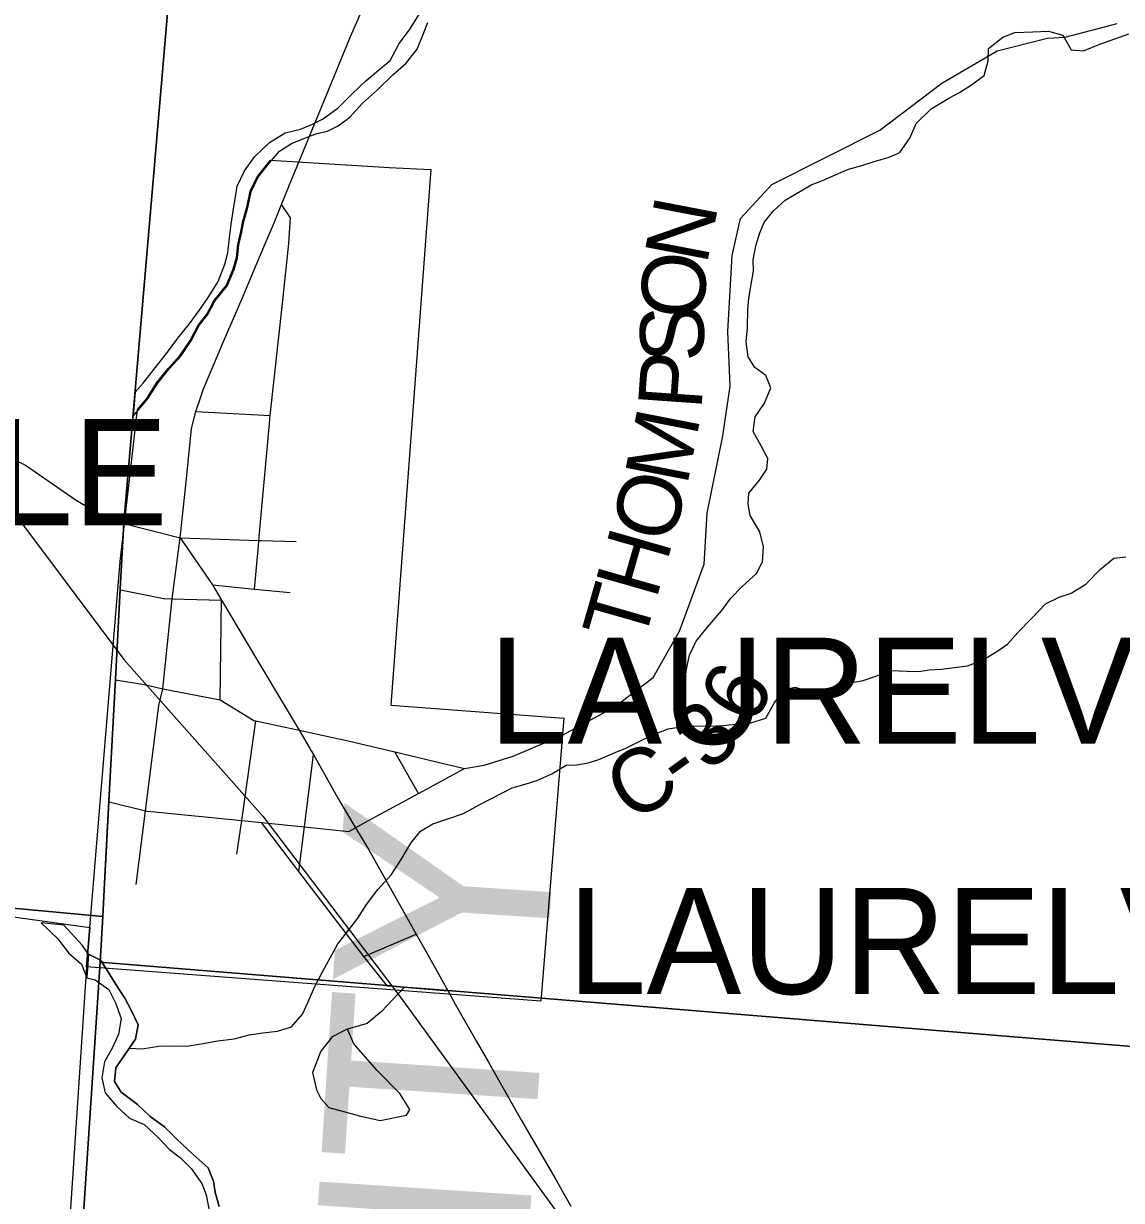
# Model space of a CAD drawing. Extents: x 0 to 42.5, y 0 to 22.
# Drawn here: x 8.135 to 8.624, y 15.489 to 16.014 of the extents above; entities that cross this region are included whole.
import ezdxf

# ---------------------------------------------------------------- set-up
doc = ezdxf.new("R2010")
doc.units = 0
for name, color, linetype in [('GM_X_City_Street', 7, 'Continuous'), ('GM_X_Corporation', 7, 'Continuous'), ('GM_X_Corporation_Text', 7, 'Continuous'), ('GM_X_County_Road', 7, 'Continuous'), ('GM_X_County_Road_Text', 7, 'Continuous'), ('GM_X_County_Text', 7, 'Continuous'), ('GM_X_Interchange_Ramps', 7, 'Continuous'), ('GM_X_Major_River', 7, 'Continuous'), ('GM_X_Minor_Lake', 7, 'Continuous'), ('GM_X_Minor_River', 7, 'Continuous'), ('GM_X_Rail_Line', 7, 'Continuous'), ('GM_X_State_Route', 7, 'Continuous'), ('GM_X_Township', 7, 'Continuous'), ('GM_X_Township_Road', 7, 'Continuous'), ('SH_Cut_Line', 7, 'Continuous')]:
    doc.layers.add(name, color=color, linetype=linetype)

msp = doc.modelspace()

# ---------------------------------------------------------------- linework, layer by layer
at = {"layer": 'GM_X_City_Street'}
for p, q in [((8.21144, 15.8409), (8.24464, 15.83913)), ((8.22234, 15.71215), (8.22295, 15.75664)), ((8.23197, 15.65827), (8.23831, 15.70274)), ((8.30735, 15.67655), (8.30026, 15.68894)), ((8.31089, 15.67036), (8.30735, 15.67655)), ((8.22983, 15.64328), (8.23197, 15.65827)), ((8.28649, 15.59759), (8.30983, 15.60755))]:
    msp.add_line(p, q, dxfattribs=at)
for points in [[(8.23767, 15.76161), (8.23941, 15.78086), (8.23963, 15.78334), (8.24416, 15.83383), (8.24464, 15.83913), (8.25024, 15.88911), (8.25294, 15.9159), (8.25382, 15.9273), (8.24973, 15.9332)], [(8.19499, 15.70965), (8.19673, 15.71712), (8.20101, 15.75731), (8.20445, 15.78454)], [(8.20445, 15.78454), (8.23963, 15.78334), (8.24068, 15.7833), (8.25621, 15.78277)], [(8.21898, 15.76345), (8.23767, 15.76161), (8.25365, 15.76011)], [(8.17086, 15.63018), (8.17281, 15.66664), (8.17572, 15.72112), (8.17786, 15.76131)], [(8.17786, 15.76131), (8.19717, 15.75743), (8.19765, 15.75742)], [(8.19765, 15.75742), (8.20101, 15.75731), (8.22295, 15.75664)], [(8.17572, 15.72112), (8.1886, 15.71895), (8.19673, 15.71712), (8.22234, 15.71215), (8.23744, 15.70293), (8.23831, 15.70274), (8.25756, 15.6986), (8.27949, 15.69389), (8.30026, 15.68894), (8.33144, 15.68151)], [(8.1849, 15.62977), (8.18905, 15.66262), (8.19499, 15.70965)], [(8.19322, 15.66218), (8.23197, 15.65827), (8.24084, 15.65737), (8.25998, 15.65544), (8.27972, 15.65345), (8.28278, 15.65511), (8.28857, 15.65825), (8.31089, 15.67036), (8.33144, 15.68151), (8.34017, 15.68308), (8.35307, 15.68696), (8.37508, 15.69643)], [(8.25754, 15.63551), (8.25998, 15.65544), (8.26395, 15.68776)], [(8.17281, 15.66664), (8.18905, 15.66262), (8.1896, 15.66255), (8.19322, 15.66218)], [(8.32405, 15.58212), (8.30443, 15.58373), (8.29698, 15.58434), (8.28649, 15.59759), (8.25754, 15.63551), (8.24084, 15.65737)]]:
    msp.add_lwpolyline(points, dxfattribs=at)
at = {"layer": 'GM_X_Corporation'}
for points in [[(8.16271, 15.59296), (8.16418, 15.61064), (8.17779, 15.77395), (8.18543, 15.84177), (8.18963, 15.84667), (8.19403, 15.85366), (8.19919, 15.86007), (8.20454, 15.86592), (8.20894, 15.87253), (8.21259, 15.87933), (8.21641, 15.88424), (8.21948, 15.89029), (8.22521, 15.89727), (8.22811, 15.90445), (8.22966, 15.90956), (8.23027, 15.91544), (8.23164, 15.92112), (8.23243, 15.92585), (8.23437, 15.93267), (8.23574, 15.93911), (8.23882, 15.94554), (8.24489, 15.95308), (8.29778, 15.94971), (8.3164, 15.94888), (8.29852, 15.70973), (8.37568, 15.70396), (8.36548, 15.57764)], [(7.91921, 15.63683), (7.95331, 15.6361), (7.97957, 15.63417), (8.04805, 15.62672), (8.16418, 15.61064), (8.16271, 15.59296), (8.14602, 15.34154), (7.89922, 15.35961), (7.91813, 15.60669)]]:
    msp.add_lwpolyline(points, close=True, dxfattribs=at)
at = {"layer": 'GM_X_County_Road'}
msp.add_lwpolyline([(8.37508, 15.69643), (8.39816, 15.70896), (8.41554, 15.7222), (8.42736, 15.7428), (8.43835, 15.7727), (8.4397, 15.7955), (8.44667, 15.82993), (8.44993, 15.85218), (8.44881, 15.87648), (8.45084, 15.91049), (8.45452, 15.92704), (8.46847, 15.94215), (8.51672, 15.96646), (8.5443, 15.98738), (8.56907, 16.00181), (8.59144, 16.00749), (8.59942, 16.00794), (8.62254, 16.01401)], dxfattribs=at)
at = {"layer": 'GM_X_Interchange_Ramps'}
for points in [[(8.24781, 16.59008), (8.17933, 15.79111), (8.17776, 15.76158), (8.17561, 15.72139), (8.1727, 15.66691), (8.17075, 15.63044), (8.16995, 15.61544), (8.16884, 15.59509), (8.29687, 15.58461), (8.30432, 15.58399), (8.32394, 15.58239), (8.67633, 15.55354), (8.9, 15.53758), (8.9, 19.05381)], [(5.08492, 14.1), (8.06989, 14.1), (8.07009, 14.10263), (8.07289, 14.12804), (8.09551, 14.48695), (8.1568, 15.41315), (8.16884, 15.59509), (8.16995, 15.61544), (8.04805, 15.62672), (7.97957, 15.63417), (7.95331, 15.6361), (7.91921, 15.63683), (7.91813, 15.60669), (7.88151, 15.60844), (7.87674, 15.60879), (7.42273, 15.64192), (7.26665, 15.65331), (5.92916, 15.74982)]]:
    msp.add_lwpolyline(points, dxfattribs=at)
msp.add_lwpolyline([(8.06989, 14.1), (8.9, 14.1), (8.9, 15.53758), (8.67633, 15.55354), (8.32394, 15.58239), (8.30432, 15.58399), (8.29687, 15.58461), (8.16884, 15.59509), (8.1568, 15.41315), (8.09551, 14.48695), (8.07289, 14.12804), (8.07009, 14.10263)], close=True, dxfattribs=at)
at = {"layer": 'GM_X_Major_River'}
for p, q in [((8.16356, 15.59873), (8.16285, 15.58805)), ((8.16897, 15.59594), (8.16356, 15.59873)), ((8.17215, 15.59118), (8.16897, 15.59594)), ((8.17571, 15.58546), (8.17215, 15.59118)), ((8.16285, 15.58805), (8.16663, 15.58723)), ((8.16663, 15.58723), (8.17266, 15.58283)), ((8.17982, 15.57899), (8.17571, 15.58546)), ((8.17266, 15.58283), (8.17564, 15.57693)), ((8.18263, 15.57366), (8.17982, 15.57899)), ((8.17564, 15.57693), (8.17824, 15.5699)), ((8.1858, 15.56719), (8.18263, 15.57366)), ((8.17824, 15.5699), (8.17706, 15.56289)), ((8.18462, 15.56075), (8.1858, 15.56719)), ((8.17706, 15.56289), (8.17436, 15.55703)), ((8.18022, 15.55452), (8.18462, 15.56075)), ((8.17436, 15.55703), (8.17072, 15.5506)), ((8.17581, 15.54792), (8.18022, 15.55452)), ((8.17072, 15.5506), (8.16953, 15.54341)), ((8.1752, 15.54185), (8.17581, 15.54792)), ((8.16953, 15.54341), (8.171, 15.53676)), ((8.1782, 15.53709), (8.1752, 15.54185)), ((8.18554, 15.53154), (8.1782, 15.53709)), ((8.171, 15.53676), (8.17626, 15.53066)), ((8.17626, 15.53066), (8.1819, 15.5255)), ((8.19118, 15.5262), (8.18554, 15.53154)), ((8.1819, 15.5255), (8.1885, 15.52261)), ((8.1885, 15.52261), (8.19471, 15.51688)), ((8.19759, 15.5216), (8.19118, 15.5262)), ((8.20304, 15.51607), (8.19759, 15.5216)), ((8.19471, 15.51688), (8.19979, 15.51154)), ((8.21037, 15.50919), (8.20304, 15.51607)), ((8.19979, 15.51154), (8.20468, 15.50771)), ((8.20468, 15.50771), (8.20938, 15.50294)), ((8.21696, 15.50327), (8.21037, 15.50919)), ((8.20938, 15.50294), (8.21425, 15.49627)), ((8.21937, 15.49738), (8.21696, 15.50327)), ((8.21425, 15.49627), (8.21611, 15.49133)), ((8.2201, 15.49244), (8.21937, 15.49738)), ((8.21611, 15.49133), (8.21739, 15.4843)), ((8.22194, 15.48598), (8.2201, 15.49244))]:
    msp.add_line(p, q, dxfattribs=at)
for points in [[(8.16356, 15.59873), (8.16897, 15.59594), (8.17215, 15.59118), (8.17571, 15.58546), (8.17982, 15.57899), (8.18263, 15.57366), (8.1858, 15.56719), (8.18462, 15.56075), (8.18022, 15.55452), (8.17581, 15.54792), (8.1752, 15.54185), (8.1782, 15.53709), (8.18554, 15.53154), (8.19118, 15.5262), (8.19759, 15.5216), (8.20304, 15.51607), (8.21037, 15.50919), (8.21696, 15.50327), (8.21937, 15.49738), (8.2201, 15.49244), (8.22194, 15.48598)], [(8.16285, 15.58805), (8.16663, 15.58723), (8.17266, 15.58283), (8.17564, 15.57693), (8.17824, 15.5699), (8.17706, 15.56289), (8.17436, 15.55703), (8.17072, 15.5506), (8.16953, 15.54341), (8.171, 15.53676), (8.17626, 15.53066), (8.1819, 15.5255), (8.1885, 15.52261), (8.19471, 15.51688), (8.19979, 15.51154), (8.20468, 15.50771), (8.20938, 15.50294), (8.21425, 15.49627), (8.21611, 15.49133), (8.21739, 15.4843)]]:
    msp.add_lwpolyline(points, dxfattribs=at)
at = {"layer": 'GM_X_Minor_Lake'}
for p, q in [((8.15269, 15.61167), (8.1425, 15.61269)), ((8.16285, 15.58805), (8.16356, 15.59873))]:
    msp.add_line(p, q, dxfattribs=at)
for points in [[(8.1425, 15.61269), (8.15, 15.60552), (8.15475, 15.59927), (8.16044, 15.59417), (8.16285, 15.58805)], [(8.16356, 15.59873), (8.1608, 15.60271), (8.15269, 15.61167)]]:
    msp.add_lwpolyline(points, dxfattribs=at)
at = {"layer": 'GM_X_Minor_River'}
for p, q in [((8.57148, 16.00789), (8.57698, 16.00994)), ((8.57698, 16.00994), (8.58494, 16.01027)), ((8.58494, 16.01027), (8.59194, 16.0106)), ((8.59194, 16.0106), (8.59837, 16.00885)), ((8.56519, 16.00281), (8.57148, 16.00789)), ((8.59837, 16.00885), (8.60211, 16.00219)), ((8.6076, 16.00178), (8.61481, 16.00476)), ((8.61481, 16.00476), (8.62146, 16.00719)), ((8.62146, 16.00719), (8.62772, 16.00942)), ((8.56496, 15.99731), (8.56519, 16.00281)), ((8.60211, 16.00219), (8.6076, 16.00178)), ((8.56321, 15.99087), (8.56496, 15.99731)), ((8.55712, 15.98636), (8.56321, 15.99087)), ((8.55217, 15.98317), (8.55712, 15.98636)), ((8.53962, 15.97586), (8.54742, 15.98074)), ((8.54742, 15.98074), (8.55217, 15.98317)), ((8.53295, 15.96945), (8.53962, 15.97586)), ((8.53006, 15.96283), (8.53295, 15.96945)), ((8.52566, 15.95641), (8.53006, 15.96283)), ((8.50858, 15.95064), (8.5137, 15.95232)), ((8.5137, 15.95232), (8.52091, 15.95436)), ((8.52091, 15.95436), (8.52566, 15.95641)), ((8.49586, 15.94599), (8.50269, 15.94898)), ((8.50269, 15.94898), (8.50858, 15.95064)), ((8.48123, 15.93925), (8.48598, 15.94207)), ((8.48598, 15.94207), (8.49111, 15.94393)), ((8.49111, 15.94393), (8.49586, 15.94599)), ((8.47438, 15.93513), (8.48123, 15.93925)), ((8.46942, 15.93061), (8.47438, 15.93513)), ((8.46522, 15.92551), (8.46942, 15.93061)), ((8.46136, 15.91473), (8.4631, 15.9206)), ((8.4631, 15.9206), (8.46522, 15.92551)), ((8.46018, 15.90848), (8.46136, 15.91473)), ((8.46033, 15.90355), (8.46018, 15.90848)), ((8.45914, 15.89673), (8.46033, 15.90355)), ((8.45816, 15.89123), (8.45914, 15.89673)), ((8.45774, 15.88631), (8.45816, 15.89123)), ((8.45769, 15.87834), (8.45774, 15.88631)), ((8.45707, 15.8719), (8.45769, 15.87834)), ((8.45797, 15.86525), (8.45707, 15.8719)), ((8.46096, 15.86049), (8.45797, 15.86525)), ((8.46586, 15.85686), (8.46096, 15.86049)), ((8.46809, 15.85135), (8.46586, 15.85686)), ((8.18452, 15.84951), (8.18361, 15.83877)), ((8.4652, 15.84454), (8.46809, 15.85135)), ((8.46099, 15.8385), (8.4652, 15.84454)), ((8.46019, 15.83186), (8.46099, 15.8385)), ((8.46393, 15.8252), (8.46019, 15.83186)), ((8.46673, 15.81987), (8.46393, 15.8252)), ((8.46632, 15.81514), (8.46673, 15.81987)), ((8.45828, 15.80438), (8.46306, 15.81023)), ((8.46306, 15.81023), (8.46632, 15.81514)), ((8.45787, 15.79945), (8.45828, 15.80438)), ((8.45878, 15.79451), (8.45787, 15.79945)), ((8.46308, 15.78709), (8.45878, 15.79451)), ((8.46474, 15.78044), (8.46308, 15.78709)), ((8.46431, 15.77381), (8.46474, 15.78044)), ((8.46162, 15.76851), (8.46431, 15.77381)), ((8.61501, 15.77036), (8.6211, 15.77544)), ((8.6211, 15.77544), (8.62641, 15.77598)), ((8.45533, 15.76268), (8.46162, 15.76851)), ((8.60852, 15.76377), (8.61501, 15.77036)), ((8.60205, 15.75983), (8.60852, 15.76377)), ((8.44598, 15.75193), (8.45018, 15.75759)), ((8.45018, 15.75759), (8.45533, 15.76268)), ((8.59066, 15.75497), (8.59674, 15.75797)), ((8.59674, 15.75797), (8.60205, 15.75983)), ((8.58455, 15.74856), (8.59066, 15.75497)), ((8.43986, 15.74457), (8.44598, 15.75193)), ((8.57826, 15.74216), (8.58455, 15.74856)), ((8.4347, 15.73834), (8.43986, 15.74457)), ((8.57368, 15.73707), (8.57826, 15.74216)), ((8.43182, 15.7321), (8.4347, 15.73834)), ((8.56892, 15.73368), (8.57368, 15.73707)), ((8.43064, 15.72661), (8.43182, 15.7321)), ((8.56245, 15.72993), (8.56892, 15.73368)), ((8.42946, 15.71998), (8.43064, 15.72661)), ((8.54425, 15.72588), (8.55107, 15.72678)), ((8.55107, 15.72678), (8.55581, 15.72732)), ((8.55581, 15.72732), (8.56245, 15.72993)), ((8.50425, 15.71988), (8.50918, 15.7208)), ((8.50918, 15.7208), (8.51582, 15.72303)), ((8.51582, 15.72303), (8.52171, 15.72526)), ((8.52171, 15.72526), (8.5289, 15.72503)), ((8.5289, 15.72503), (8.53401, 15.72481)), ((8.53401, 15.72481), (8.53875, 15.72553)), ((8.53875, 15.72553), (8.54425, 15.72588)), ((8.42865, 15.71259), (8.42946, 15.71998)), ((8.46953, 15.71062), (8.47393, 15.71685)), ((8.47393, 15.71685), (8.47886, 15.71777)), ((8.47886, 15.71777), (8.48434, 15.71621)), ((8.48434, 15.71621), (8.49135, 15.71655)), ((8.49135, 15.71655), (8.49685, 15.71765)), ((8.49685, 15.71765), (8.50425, 15.71988)), ((8.42765, 15.70558), (8.42865, 15.71259)), ((8.46589, 15.70401), (8.46953, 15.71062)), ((8.42752, 15.70006), (8.42765, 15.70558)), ((8.4223, 15.69917), (8.42875, 15.70027)), ((8.42875, 15.70027), (8.43348, 15.70061)), ((8.43348, 15.70061), (8.44011, 15.70038)), ((8.44011, 15.70038), (8.44674, 15.70072)), ((8.44674, 15.70072), (8.45356, 15.70143)), ((8.45356, 15.70143), (8.45868, 15.70178)), ((8.45868, 15.70178), (8.46589, 15.70401)), ((8.40996, 15.69394), (8.41547, 15.69656)), ((8.41547, 15.69656), (8.4223, 15.69917)), ((8.39856, 15.6887), (8.4033, 15.69057)), ((8.4033, 15.69057), (8.40996, 15.69394)), ((8.38148, 15.68312), (8.3866, 15.68404)), ((8.3866, 15.68404), (8.39134, 15.68553)), ((8.39134, 15.68553), (8.39856, 15.6887)), ((8.36363, 15.67622), (8.37028, 15.67921)), ((8.37028, 15.67921), (8.37674, 15.68297)), ((8.37674, 15.68297), (8.38148, 15.68312)), ((8.35262, 15.67288), (8.3585, 15.67455)), ((8.3585, 15.67455), (8.36363, 15.67622)), ((8.34312, 15.66801), (8.35262, 15.67288)), ((8.33095, 15.66145), (8.33818, 15.66539)), ((8.33818, 15.66539), (8.34312, 15.66801)), ((8.31729, 15.6568), (8.32393, 15.65903)), ((8.32393, 15.65903), (8.33095, 15.66145)), ((8.30738, 15.64814), (8.31177, 15.65361)), ((8.31177, 15.65361), (8.31729, 15.6568)), ((8.30316, 15.64096), (8.30738, 15.64814)), ((8.29876, 15.63416), (8.30316, 15.64096)), ((8.29265, 15.62757), (8.29876, 15.63416)), ((8.28768, 15.62077), (8.29265, 15.62757)), ((8.28385, 15.61473), (8.28768, 15.62077)), ((8.27869, 15.60812), (8.28385, 15.61473)), ((8.27486, 15.60322), (8.27869, 15.60812)), ((8.27218, 15.5983), (8.27486, 15.60322)), ((8.26815, 15.59112), (8.27218, 15.5983)), ((8.2645, 15.58394), (8.26815, 15.59112)), ((8.26161, 15.57732), (8.2645, 15.58394)), ((8.25911, 15.57184), (8.26161, 15.57732)), ((8.25415, 15.56618), (8.25911, 15.57184)), ((8.23537, 15.5627), (8.24144, 15.56361)), ((8.24144, 15.56361), (8.24788, 15.56433)), ((8.24788, 15.56433), (8.25415, 15.56618)), ((8.2075, 15.55757), (8.21395, 15.55867)), ((8.21395, 15.55867), (8.22134, 15.55995)), ((8.22134, 15.55995), (8.22855, 15.56085)), ((8.22855, 15.56085), (8.23537, 15.5627)), ((8.18172, 15.55665), (8.18761, 15.55637)), ((8.18761, 15.55637), (8.19501, 15.55765)), ((8.19501, 15.55765), (8.20069, 15.5578)), ((8.20069, 15.5578), (8.2075, 15.55757))]:
    msp.add_line(p, q, dxfattribs=at)
for points in [[(8.18452, 15.84951), (8.18807, 15.85354), (8.19284, 15.85958), (8.19839, 15.86675), (8.20355, 15.87354), (8.20852, 15.87977), (8.21349, 15.88656), (8.21732, 15.89223), (8.22153, 15.89884), (8.22443, 15.90659), (8.22579, 15.9117), (8.22659, 15.91834), (8.22721, 15.9244), (8.22819, 15.93027), (8.22919, 15.93672), (8.22998, 15.94145), (8.23325, 15.94826), (8.23784, 15.95467), (8.24432, 15.96089), (8.25136, 15.96521), (8.25819, 15.96687), (8.26332, 15.96892), (8.26807, 15.97136), (8.27492, 15.97624), (8.28121, 15.98265), (8.28732, 15.98849), (8.29208, 15.99244), (8.29817, 15.99752), (8.3022, 16.00508), (8.30679, 16.01112), (8.31101, 16.01792)], [(8.18361, 15.83877), (8.1859, 15.84161), (8.1901, 15.84651), (8.1945, 15.8535), (8.19966, 15.85991), (8.20501, 15.86576), (8.20941, 15.87237), (8.21306, 15.87917), (8.21688, 15.88407), (8.21995, 15.89012), (8.22568, 15.8971), (8.22857, 15.90429), (8.23013, 15.9094), (8.23074, 15.91528), (8.2321, 15.92096), (8.23289, 15.92569), (8.23484, 15.93251), (8.23621, 15.93895), (8.23929, 15.94537), (8.24445, 15.95179), (8.24884, 15.95707), (8.25417, 15.96045), (8.26043, 15.96306), (8.26556, 15.96493), (8.2703, 15.96603), (8.27505, 15.96828), (8.28019, 15.97223), (8.28592, 15.97845), (8.29259, 15.98447), (8.29945, 15.99107), (8.30517, 15.99615), (8.31033, 16.00256), (8.31245, 16.00805), (8.31496, 16.01448)]]:
    msp.add_lwpolyline(points, dxfattribs=at)
at = {"layer": 'GM_X_Rail_Line'}
for points in [[(7.98347, 16.32444), (7.94829, 15.9349), (7.95454, 15.91522), (7.97421, 15.89822), (8.00014, 15.88211), (8.09048, 15.83928), (8.11148, 15.82198), (8.12531, 15.80248), (8.17938, 15.73019)], [(8.17938, 15.73019), (8.24138, 15.6602), (8.30262, 15.57959), (8.42318, 15.41403), (8.46804, 15.38328), (8.66065, 15.25025), (8.9, 15.08301)]]:
    msp.add_lwpolyline(points, dxfattribs=at)
at = {"layer": 'GM_X_State_Route'}
msp.add_line((8.17944, 15.79084), (8.20445, 15.78454), dxfattribs=at)
for points in [[(8.25314, 15.94167), (8.25459, 15.94526), (8.26156, 15.96227), (8.26969, 15.98172), (8.28054, 16.00817), (8.29059, 16.03121)], [(8.242, 15.91462), (8.24645, 15.92505), (8.24973, 15.9332), (8.25296, 15.94122), (8.25314, 15.94167)], [(8.21369, 15.84735), (8.21471, 15.85024), (8.22381, 15.87216), (8.23213, 15.89123), (8.23871, 15.90691), (8.242, 15.91462)], [(8.00999, 15.84744), (8.04008, 15.84735), (8.07009, 15.84292), (8.10108, 15.83357), (8.13551, 15.81685), (8.15807, 15.80127), (8.17068, 15.79387), (8.17944, 15.79084)], [(8.20445, 15.78454), (8.20734, 15.81087), (8.20963, 15.83322), (8.21144, 15.8409), (8.21355, 15.84694), (8.21369, 15.84735)], [(8.20445, 15.78454), (8.21898, 15.76345), (8.22295, 15.75664), (8.23879, 15.7302), (8.25091, 15.7098), (8.25756, 15.6986), (8.26225, 15.69072)], [(8.26225, 15.69072), (8.26303, 15.68941), (8.26395, 15.68776), (8.27533, 15.66749), (8.28278, 15.65511), (8.28876, 15.64519), (8.30086, 15.62347), (8.30983, 15.60755), (8.31353, 15.60098), (8.32405, 15.58212), (8.32642, 15.57787), (8.32666, 15.57743)], [(8.32666, 15.57743), (8.32788, 15.57525), (8.33658, 15.56004)], [(8.33658, 15.56004), (8.34204, 15.55048), (8.35676, 15.52437), (8.37168, 15.49883), (8.37878, 15.48616)]]:
    msp.add_lwpolyline(points, dxfattribs=at)
at = {"layer": 'GM_X_Township'}
msp.add_lwpolyline([(8.24781, 16.59008), (8.17933, 15.79111), (8.17776, 15.76158), (8.17561, 15.72139), (8.1727, 15.66691), (8.17075, 15.63044), (8.16995, 15.61544), (8.04805, 15.62672), (7.97957, 15.63417), (7.95331, 15.6361), (7.91921, 15.63683), (7.91813, 15.60669), (7.88151, 15.60844), (7.87674, 15.60879), (7.42273, 15.64192), (7.26665, 15.65331), (5.92916, 15.74982), (5.21422, 15.79865), (5.23885, 16.11392)], dxfattribs=at)
at = {"layer": 'GM_X_Township_Road'}
for points in [[(8.30443, 15.58373), (8.2943, 15.57312), (8.28788, 15.56775), (8.27916, 15.56513), (8.27879, 15.56503), (8.27235, 15.56175), (8.26727, 15.55544), (8.26354, 15.54592), (8.2653, 15.53815), (8.26723, 15.53418), (8.27087, 15.53022), (8.28457, 15.52652), (8.2937, 15.5245), (8.30546, 15.52687)], [(8.30546, 15.52687), (8.30696, 15.52935), (8.30254, 15.53653), (8.2924, 15.54671), (8.28206, 15.55859), (8.27916, 15.56513)]]:
    msp.add_lwpolyline(points, dxfattribs=at)
at = {"layer": 'SH_Cut_Line'}
for points in [[(8.24781, 16.59008), (8.17933, 15.79111), (8.17776, 15.76158), (8.17561, 15.72139), (8.1727, 15.66691), (8.17075, 15.63044), (8.16995, 15.61544), (8.16884, 15.59509), (8.1568, 15.41315), (8.09551, 14.48695), (8.07289, 14.12804), (8.07009, 14.10263), (8.06989, 14.1), (8.9, 14.1), (8.9, 19.05381)], [(3.72132, 15.90374), (4.44374, 15.85348), (4.57597, 15.84389), (4.70326, 15.83465), (4.83401, 15.82463), (5.0466, 15.8101), (5.21422, 15.79865), (5.92916, 15.74982), (7.26665, 15.65331), (7.42273, 15.64192), (7.87674, 15.60879), (7.88151, 15.60844), (7.91813, 15.60669), (7.91921, 15.63683), (7.95331, 15.6361), (7.97957, 15.63417), (8.04805, 15.62672), (8.16995, 15.61544), (8.17075, 15.63044), (8.1727, 15.66691), (8.17561, 15.72139), (8.17776, 15.76158), (8.17933, 15.79111), (8.24781, 16.59008)], [(2.1, 14.1), (8.06989, 14.1), (8.07009, 14.10263), (8.07289, 14.12804), (8.09551, 14.48695), (8.1568, 15.41315), (8.16884, 15.59509), (8.16995, 15.61544), (8.04805, 15.62672), (7.97957, 15.63417), (7.95331, 15.6361), (7.91921, 15.63683), (7.91813, 15.60669), (7.88151, 15.60844), (7.87674, 15.60879), (7.42273, 15.64192), (7.26665, 15.65331), (5.92916, 15.74982)]]:
    msp.add_lwpolyline(points, dxfattribs=at)

# ---------------------------------------------------------------- texts
at = {"layer": 'GM_X_Corporation_Text'}
for p in [(7.78018, 15.7901), (8.34215, 15.69254), (8.37738, 15.58087)]:
    msp.add_text('LAURELVILLE', height=0.0473485, rotation=0, dxfattribs=at).set_placement(p)
at = {"layer": 'GM_X_County_Road_Text'}
for s, rotation, p in [('N', 79.1044, (8.43945, 15.90579)), ('O', 86.4205, (8.43801, 15.88179)), ('S', 91.3193, (8.43846, 15.86327)), ('P', 85.9882, (8.43705, 15.84126)), ('M', 78.9483, (8.43064, 15.80723)), ('O', 75.4079, (8.42392, 15.78116)), ('H', 74.0476, (8.41685, 15.75642)), ('T', 74.0052, (8.41099, 15.73597)), ('6', 62.5986, (8.46019, 15.69979)), ('3', 42.0776, (8.44044, 15.67931)), ('C', 29.7294, (8.4053, 15.65702)), ('-', 35.7055, (8.42828, 15.67034))]:
    msp.add_text(s, height=0.02841, rotation=rotation, dxfattribs=at).set_placement(p)
at = {"layer": 'GM_X_County_Text'}
msp.add_text('HOCKING COUNTY', height=0.094697, rotation=86.2285, dxfattribs=at).set_placement((8.29618, 14.5044))

doc.saveas('drawing.dxf')
